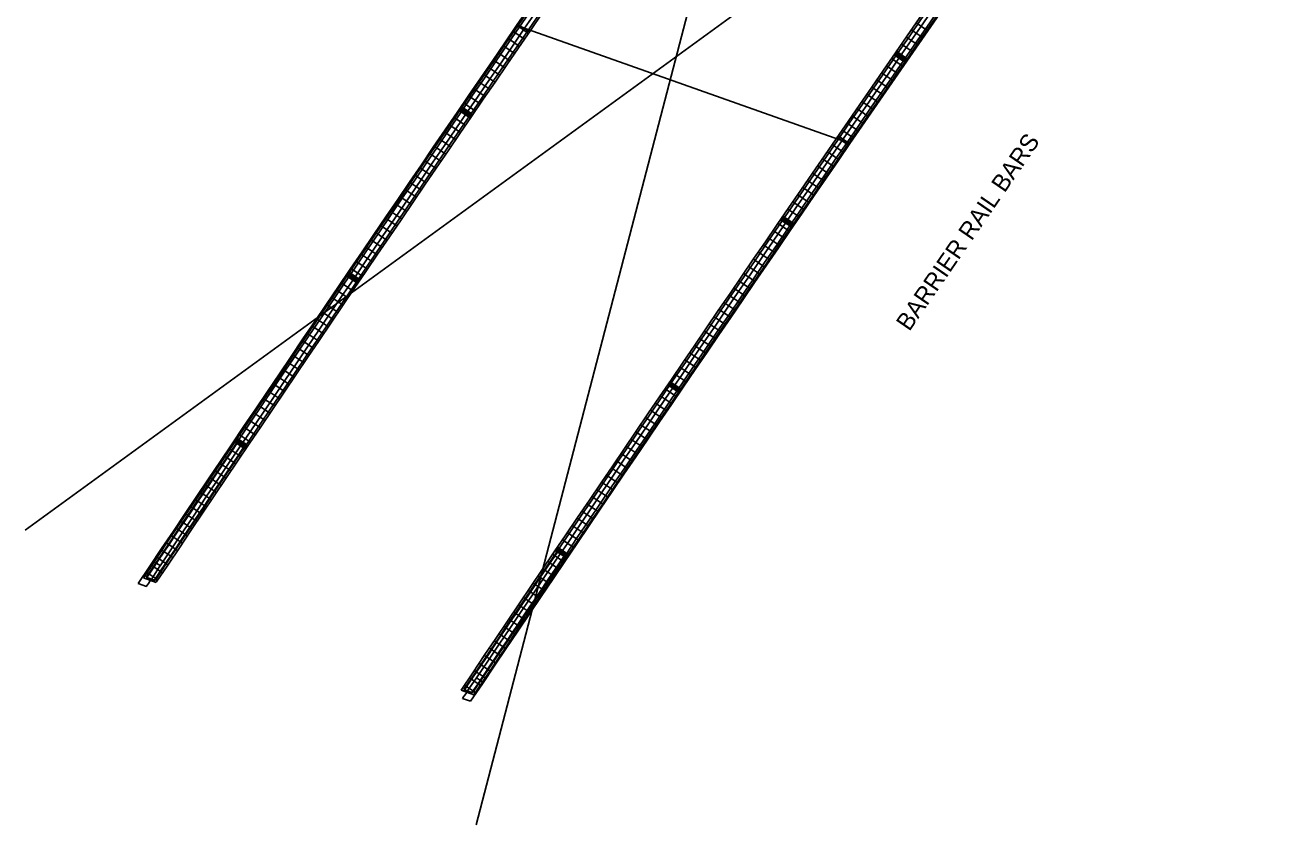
# Model space of a CAD drawing. Extents: x 2378999 to 2381348, y 331302 to 333122.
# Drawn here: x 2380145.5 to 2380290.4, y 332525.5 to 332617.4 of the extents above; entities that cross this region are included whole.
import ezdxf

# ---------------------------------------------------------------- set-up
doc = ezdxf.new("R2010")
doc.units = 0
for name, color, linetype in [('Arrowhead Terminators', 7, 'Continuous'), ('Dimension Lines', 7, 'Continuous'), ('Mis Work Point CELL', 7, 'Continuous'), ('P_SMU_Centerline_Joint', 7, 'Continuous'), ('P_SMU_Concrete_Barrier_Rail', 7, 'Continuous'), ('P_SMU_Mis_Center_Lines', 7, 'Continuous'), ('Scratch_Level_0', 7, 'Continuous'), ('Sup Concrete Slab Lines', 7, 'Continuous')]:
    doc.layers.add(name, color=color, linetype=linetype)

msp = doc.modelspace()

# ---------------------------------------------------------------- linework, layer by layer
at = {"layer": 'Arrowhead Terminators'}
for radius, start, end in [(7099.19, 146.01707, 146.167847), (7098.31, 146.01707, 146.166041), (7061.69, 145.935062, 146.090044), (7060.81, 145.935062, 146.088218)]:
    msp.add_arc((2386056.55, 328601.34), radius, start, end, dxfattribs=at)
at = {"layer": 'Dimension Lines'}
for p, q in [((2380202.16, 332617.43), (2380203.4, 332616.59)), ((2380247.85, 332617.66), (2380249.08, 332616.81)), ((2380201.03, 332615.79), (2380202.27, 332614.94)), ((2380201.6, 332616.61), (2380202.83, 332615.76)), ((2380246.71, 332616.01), (2380247.95, 332615.16)), ((2380247.28, 332616.84), (2380248.52, 332615.98)), ((2380200.47, 332614.96), (2380201.7, 332614.11)), ((2380245.58, 332614.37), (2380246.81, 332613.52)), ((2380246.14, 332615.19), (2380247.38, 332614.34)), ((2380199.34, 332613.31), (2380200.57, 332612.46)), ((2380199.9, 332614.14), (2380201.14, 332613.29)), ((2380245.01, 332613.55), (2380246.24, 332612.69)), ((2380198.21, 332611.66), (2380199.44, 332610.81)), ((2380198.77, 332612.49), (2380200.01, 332611.64)), ((2380243.87, 332611.9), (2380245.11, 332611.05)), ((2380244.44, 332612.72), (2380245.67, 332611.87)), ((2380197.08, 332610.01), (2380198.31, 332609.16)), ((2380197.64, 332610.84), (2380198.88, 332609.99)), ((2380242.74, 332610.25), (2380243.97, 332609.4)), ((2380243.3, 332611.08), (2380244.54, 332610.22)), ((2380196.51, 332609.18), (2380197.75, 332608.34)), ((2380241.6, 332608.61), (2380242.84, 332607.75)), ((2380242.17, 332609.43), (2380243.4, 332608.58)), ((2380195.38, 332607.53), (2380196.62, 332606.69)), ((2380195.95, 332608.36), (2380197.19, 332607.51)), ((2380241.03, 332607.78), (2380242.27, 332606.93)), ((2380194.25, 332605.88), (2380195.49, 332605.04)), ((2380194.82, 332606.71), (2380196.06, 332605.86)), ((2380239.9, 332606.13), (2380241.13, 332605.28)), ((2380240.47, 332606.96), (2380241.7, 332606.11)), ((2380193.13, 332604.23), (2380194.37, 332603.39)), ((2380193.69, 332605.06), (2380194.93, 332604.21)), ((2380238.76, 332604.49), (2380240, 332603.64)), ((2380239.33, 332605.31), (2380240.57, 332604.46)), ((2380192.56, 332603.4), (2380193.8, 332602.56)), ((2380237.63, 332602.84), (2380238.87, 332601.99)), ((2380238.2, 332603.66), (2380239.43, 332602.81)), ((2380191.44, 332601.75), (2380192.68, 332600.91)), ((2380192, 332602.58), (2380193.24, 332601.73)), ((2380237.06, 332602.01), (2380238.3, 332601.16)), ((2380190.31, 332600.1), (2380191.55, 332599.26)), ((2380190.87, 332600.93), (2380192.11, 332600.08)), ((2380235.93, 332600.37), (2380237.17, 332599.52)), ((2380236.5, 332601.19), (2380237.73, 332600.34)), ((2380189.18, 332598.45), (2380190.42, 332597.6)), ((2380189.75, 332599.27), (2380190.99, 332598.43)), ((2380234.8, 332598.72), (2380236.03, 332597.87)), ((2380235.36, 332599.54), (2380236.6, 332598.69)), ((2380188.62, 332597.62), (2380189.86, 332596.78)), ((2380233.67, 332597.07), (2380234.9, 332596.22)), ((2380234.23, 332597.89), (2380235.47, 332597.04)), ((2380187.49, 332595.97), (2380188.73, 332595.12)), ((2380188.06, 332596.79), (2380189.3, 332595.95)), ((2380233.1, 332596.24), (2380234.34, 332595.39)), ((2380186.37, 332594.31), (2380187.61, 332593.47)), ((2380186.93, 332595.14), (2380188.17, 332594.3)), ((2380231.97, 332594.59), (2380233.21, 332593.74)), ((2380232.53, 332595.42), (2380233.77, 332594.57)), ((2380185.24, 332592.66), (2380186.49, 332591.82)), ((2380185.81, 332593.49), (2380187.05, 332592.64)), ((2380230.84, 332592.94), (2380232.08, 332592.09)), ((2380231.4, 332593.77), (2380232.64, 332592.92)), ((2380184.68, 332591.83), (2380185.92, 332590.99)), ((2380229.71, 332591.29), (2380230.95, 332590.44)), ((2380230.27, 332592.12), (2380231.51, 332591.27)), ((2380183.56, 332590.18), (2380184.8, 332589.34)), ((2380184.12, 332591.01), (2380185.36, 332590.16)), ((2380229.14, 332590.47), (2380230.38, 332589.62)), ((2380182.44, 332588.52), (2380183.68, 332587.68)), ((2380183, 332589.35), (2380184.24, 332588.51)), ((2380228.01, 332588.82), (2380229.25, 332587.97)), ((2380228.58, 332589.64), (2380229.82, 332588.79)), ((2380181.31, 332586.87), (2380182.55, 332586.03)), ((2380181.87, 332587.7), (2380183.11, 332586.85)), ((2380226.88, 332587.16), (2380228.12, 332586.32)), ((2380227.45, 332587.99), (2380228.69, 332587.14)), ((2380180.75, 332586.04), (2380181.99, 332585.2)), ((2380225.75, 332585.51), (2380226.99, 332584.67)), ((2380226.32, 332586.34), (2380227.56, 332585.49)), ((2380179.63, 332584.39), (2380180.87, 332583.54)), ((2380180.19, 332585.21), (2380181.43, 332584.37)), ((2380225.19, 332584.69), (2380226.43, 332583.84)), ((2380178.51, 332582.73), (2380179.75, 332581.89)), ((2380179.07, 332583.56), (2380180.31, 332582.72)), ((2380224.06, 332583.04), (2380225.3, 332582.19)), ((2380224.63, 332583.86), (2380225.87, 332583.02)), ((2380177.39, 332581.07), (2380178.63, 332580.23)), ((2380177.95, 332581.9), (2380179.19, 332581.06)), ((2380222.93, 332581.38), (2380224.17, 332580.54)), ((2380223.5, 332582.21), (2380224.74, 332581.36)), ((2380176.82, 332580.25), (2380178.07, 332579.41)), ((2380221.81, 332579.73), (2380223.05, 332578.89)), ((2380222.37, 332580.56), (2380223.61, 332579.71)), ((2380175.7, 332578.59), (2380176.95, 332577.75)), ((2380176.26, 332579.42), (2380177.51, 332578.58)), ((2380220.68, 332578.08), (2380221.92, 332577.23)), ((2380221.24, 332578.9), (2380222.48, 332578.06)), ((2380174.58, 332576.93), (2380175.83, 332576.09)), ((2380175.14, 332577.76), (2380176.39, 332576.92)), ((2380220.12, 332577.25), (2380221.36, 332576.41)), ((2380173.46, 332575.28), (2380174.71, 332574.44)), ((2380174.02, 332576.1), (2380175.27, 332575.26)), ((2380218.99, 332575.6), (2380220.23, 332574.75)), ((2380219.55, 332576.42), (2380220.79, 332575.58)), ((2380172.9, 332574.45), (2380174.15, 332573.61)), ((2380217.87, 332573.94), (2380219.11, 332573.1)), ((2380218.43, 332574.77), (2380219.67, 332573.93)), ((2380171.79, 332572.79), (2380173.03, 332571.95)), ((2380172.34, 332573.62), (2380173.59, 332572.78)), ((2380216.74, 332572.29), (2380217.98, 332571.45)), ((2380217.3, 332573.12), (2380218.54, 332572.27)), ((2380170.67, 332571.13), (2380171.91, 332570.29)), ((2380171.23, 332571.96), (2380172.47, 332571.12)), ((2380216.18, 332571.46), (2380217.42, 332570.62)), ((2380169.55, 332569.47), (2380170.79, 332568.64)), ((2380170.11, 332570.3), (2380171.35, 332569.46)), ((2380215.05, 332569.81), (2380216.3, 332568.97)), ((2380215.62, 332570.64), (2380216.86, 332569.79)), ((2380168.99, 332568.64), (2380170.23, 332567.81)), ((2380213.93, 332568.15), (2380215.17, 332567.31)), ((2380214.49, 332568.98), (2380215.73, 332568.14)), ((2380167.87, 332566.99), (2380169.12, 332566.15)), ((2380168.43, 332567.81), (2380169.68, 332566.98)), ((2380212.81, 332566.5), (2380214.05, 332565.66)), ((2380213.37, 332567.33), (2380214.61, 332566.48)), ((2380166.76, 332565.33), (2380168, 332564.49)), ((2380167.31, 332566.16), (2380168.56, 332565.32)), ((2380212.25, 332565.67), (2380213.49, 332564.83)), ((2380165.64, 332563.67), (2380166.88, 332562.83)), ((2380166.2, 332564.5), (2380167.44, 332563.66)), ((2380211.12, 332564.01), (2380212.36, 332563.17)), ((2380211.68, 332564.84), (2380212.93, 332564)), ((2380165.08, 332562.84), (2380166.33, 332562)), ((2380210, 332562.36), (2380211.24, 332561.52)), ((2380210.56, 332563.19), (2380211.8, 332562.35)), ((2380163.97, 332561.18), (2380165.21, 332560.34)), ((2380164.52, 332562.01), (2380165.77, 332561.17)), ((2380208.88, 332560.7), (2380210.12, 332559.86)), ((2380209.44, 332561.53), (2380210.68, 332560.69)), ((2380162.85, 332559.52), (2380164.1, 332558.68)), ((2380163.41, 332560.35), (2380164.65, 332559.51)), ((2380208.32, 332559.87), (2380209.56, 332559.03)), ((2380161.74, 332557.86), (2380162.98, 332557.02)), ((2380162.29, 332558.69), (2380163.54, 332557.85)), ((2380207.2, 332558.22), (2380208.44, 332557.38)), ((2380207.76, 332559.05), (2380209, 332558.21)), ((2380161.18, 332557.03), (2380162.42, 332556.19)), ((2380206.08, 332556.56), (2380207.32, 332555.72)), ((2380206.64, 332557.39), (2380207.88, 332556.55)), ((2380160.01, 332555.29), (2380161.26, 332554.45)), ((2380160.62, 332556.2), (2380161.87, 332555.36)), ((2380204.96, 332554.9), (2380206.2, 332554.06)), ((2380205.52, 332555.73), (2380206.76, 332554.89)), ((2380159.45, 332554.46), (2380160.7, 332553.62)), ((2380204.4, 332554.07), (2380205.64, 332553.23)), ((2380203.28, 332552.42), (2380204.52, 332551.58)), ((2380203.84, 332553.25), (2380205.08, 332552.41)), ((2380202.16, 332550.76), (2380203.4, 332549.92)), ((2380202.72, 332551.59), (2380203.96, 332550.75)), ((2380201.04, 332549.1), (2380202.28, 332548.26)), ((2380201.6, 332549.93), (2380202.84, 332549.09)), ((2380200.48, 332548.27), (2380201.72, 332547.43)), ((2380199.36, 332546.61), (2380200.61, 332545.77)), ((2380199.92, 332547.44), (2380201.17, 332546.6)), ((2380198.25, 332544.95), (2380199.49, 332544.11)), ((2380198.8, 332545.78), (2380200.05, 332544.94)), ((2380197.63, 332544.03), (2380198.87, 332543.19)), ((2380196.51, 332542.37), (2380197.75, 332541.53)), ((2380197.07, 332543.2), (2380198.31, 332542.36)), ((2380195.95, 332541.54), (2380197.2, 332540.7))]:
    msp.add_line(p, q, dxfattribs=at)
at = {"layer": 'Mis Work Point CELL'}
msp.add_line((2380201.94, 332617.32), (2380240.24, 332603.77), dxfattribs=at)
at = {"layer": 'P_SMU_Centerline_Joint'}
for p, q in [((2380203.29, 332616.43), (2380202.06, 332617.28)), ((2380245.41, 332614.13), (2380246.65, 332613.28)), ((2380196.8, 332606.94), (2380195.56, 332607.79)), ((2380238.88, 332604.66), (2380240.12, 332603.81)), ((2380232.37, 332595.18), (2380233.61, 332594.33)), ((2380183.85, 332587.94), (2380182.61, 332588.78)), ((2380219.39, 332576.18), (2380220.63, 332575.34)), ((2380170.97, 332568.89), (2380169.72, 332569.73)), ((2380206.47, 332557.15), (2380207.72, 332556.31))]:
    msp.add_line(p, q, dxfattribs=at)
at = {"layer": 'P_SMU_Concrete_Barrier_Rail'}
for p, q in [((2380197.3, 332525.48), (2380243.02, 332701.32)), ((2380145.47, 332559.34), (2380290.42, 332664.83)), ((2380158.46, 332553.19), (2380159.39, 332552.86)), ((2380196.65, 332539.67), (2380195.72, 332540))]:
    msp.add_line(p, q, dxfattribs=at)
for radius, start, end in [(7099.63, 144.926438, 146.177079), (7060.38, 144.837589, 146.095684), (7098.67, 146.168161, 146.175103), (7061.33, 146.090701, 146.097683)]:
    msp.add_arc((2386056.55, 328601.34), radius, start, end, dxfattribs=at)
at = {"layer": 'P_SMU_Mis_Center_Lines'}
for p, q in [((2380245.4, 332614.11), (2380246.63, 332613.26)), ((2380245.42, 332614.15), (2380246.66, 332613.29)), ((2380196.79, 332606.93), (2380195.55, 332607.77)), ((2380196.81, 332606.96), (2380195.57, 332607.81)), ((2380232.36, 332595.16), (2380233.6, 332594.31)), ((2380232.38, 332595.2), (2380233.62, 332594.35)), ((2380183.84, 332587.92), (2380182.6, 332588.76)), ((2380183.86, 332587.96), (2380182.62, 332588.8)), ((2380219.38, 332576.17), (2380220.62, 332575.32)), ((2380219.4, 332576.2), (2380220.64, 332575.36)), ((2380170.95, 332568.88), (2380169.71, 332569.71)), ((2380170.98, 332568.91), (2380169.73, 332569.75)), ((2380206.46, 332557.13), (2380207.7, 332556.29)), ((2380206.49, 332557.17), (2380207.73, 332556.33)), ((2380159.91, 332553.56), (2380160.97, 332555.26)), ((2380160.97, 332555.26), (2380160.29, 332555.71)), ((2380160.51, 332553.34), (2380159.06, 332553.86)), ((2380197.33, 332542.35), (2380196.16, 332540.73)), ((2380197.33, 332542.35), (2380198, 332541.9)), ((2380195.55, 332540.94), (2380197.01, 332540.43))]:
    msp.add_line(p, q, dxfattribs=at)
for radius, start, end in [(7099.5, 144.933138, 146.16988), (7098, 144.929763, 146.166785), (7098.69, 144.947312, 146.151932), (7062, 144.84831, 146.092092), (7060.5, 144.844897, 146.088963), (7061.31, 144.863116, 146.07456)]:
    msp.add_arc((2386056.55, 328601.34), radius, start, end, dxfattribs=at)
at = {"layer": 'Scratch_Level_0'}
for p, q in [((2380245.3, 332613.98), (2380246.54, 332613.12)), ((2380245.52, 332614.28), (2380246.75, 332613.43)), ((2380196.69, 332606.79), (2380195.45, 332607.64)), ((2380196.9, 332607.1), (2380195.66, 332607.95)), ((2380232.26, 332595.02), (2380233.5, 332594.18)), ((2380232.48, 332595.33), (2380233.71, 332594.48)), ((2380183.75, 332587.78), (2380182.5, 332588.63)), ((2380183.96, 332588.09), (2380182.72, 332588.94)), ((2380219.29, 332576.03), (2380220.53, 332575.19)), ((2380219.5, 332576.34), (2380220.74, 332575.5)), ((2380170.86, 332568.74), (2380169.62, 332569.58)), ((2380171.07, 332569.05), (2380169.83, 332569.89)), ((2380206.37, 332556.99), (2380207.61, 332556.15)), ((2380206.58, 332557.3), (2380207.82, 332556.46)), ((2380160.39, 332553.57), (2380159.37, 332553.93)), ((2380195.87, 332541.01), (2380196.88, 332540.65))]:
    msp.add_line(p, q, dxfattribs=at)
for radius, start, end in [(7099.27, 144.934019, 146.168019), (7098.23, 144.931676, 146.165869), (7061.77, 144.849193, 146.090218), (7060.73, 144.846823, 146.088044)]:
    msp.add_arc((2386056.55, 328601.34), radius, start, end, dxfattribs=at)

# ---------------------------------------------------------------- texts
at = {"layer": 'Sup Concrete Slab Lines'}
msp.add_text('BARRIER RAIL BARS', height=2, rotation=55.5093, dxfattribs=at).set_placement((2380247.05, 332582.1))

doc.saveas('drawing.dxf')
